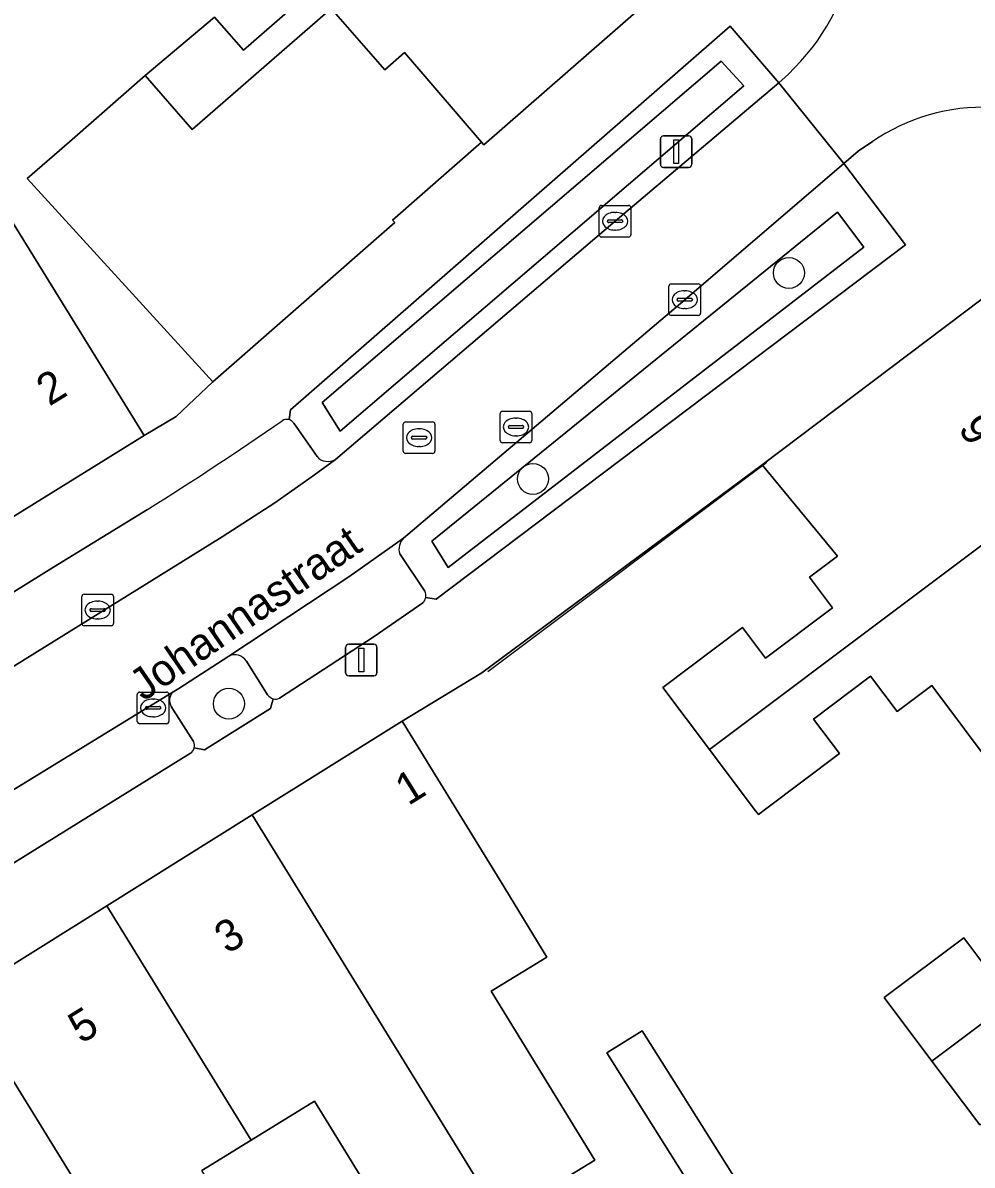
# Model space of a CAD drawing. Extents: x 159716 to 160783, y 383290 to 384031.
# Drawn here: x 160498.53 to 160528.52, y 383488.74 to 383524.87 of the extents above; entities that cross this region are included whole.
import ezdxf

# ---------------------------------------------------------------- set-up
doc = ezdxf.new("R2010")
doc.units = 0
for name, color, linetype in [('IMGEO_Boom', 7, 'Continuous'), ('IMGEO_Erf', 7, 'Continuous'), ('IMGEO_Groenvoorziening', 7, 'Continuous'), ('IMGEO_Kolk', 7, 'Continuous'), ('IMGEO_Lichtmast', 7, 'Continuous'), ('IMGEO_Muur', 7, 'Continuous'), ('IMGEO_Openbare_ruimte_label', 7, 'Continuous'), ('IMGEO_Pand', 7, 'Continuous'), ('IMGEO_Pand_nummerreeks', 7, 'Continuous'), ('IMGEO_Parkeervlak_open', 7, 'Continuous'), ('IMGEO_Rijbaan_lokaal_open', 7, 'Continuous'), ('IMGEO_Rioolput', 7, 'Continuous'), ('IMGEO_Voetpad_open', 7, 'Continuous')]:
    doc.layers.add(name, color=color, linetype=linetype)

msp = doc.modelspace()

# ---------------------------------------------------------------- linework, layer by layer
at = {"layer": 'IMGEO_Boom'}
for centre in [(160522.734, 383516.956), (160514.646, 383510.442), (160505.036, 383503.334)]:
    msp.add_circle(centre, 0.489, dxfattribs=at)
at = {"layer": 'IMGEO_Erf'}
for points in [[(160474.442, 383512.059), (160477.722, 383506.738), (160479.584, 383507.886), (160481.047, 383508.788), (160477.74, 383514.152), (160480.93, 383516.118), (160483.558, 383517.738), (160486.817, 383512.452), (160488.841, 383513.7), (160490.206, 383514.541), (160486.892, 383519.915), (160490.181, 383521.943), (160492.677, 383523.481), (160496.006, 383518.081), (160497.813, 383519.195), (160502.361, 383511.817), (160503.371, 383512.413), (160504.529, 383513.509), (160498.663, 383519.938), (160500, 383521.105), (160502.393, 383523.195), (160504.587, 383525.045), (160505.499, 383524.004), (160507.373, 383525.646)], [(160529.316, 383501.144), (160527.247, 383503.907), (160526.151, 383503.084), (160525.312, 383504.201), (160523.511, 383502.849), (160524.333, 383501.754), (160521.998, 383500), (160521.768, 383499.827), (160521.638, 383500), (160520.224, 383501.882), (160518.745, 383503.851), (160521.263, 383505.742), (160521.989, 383504.774), (160524.107, 383506.365), (160523.38, 383507.332), (160524.267, 383507.998), (160521.892, 383510.886), (160513.025, 383504.314), (160510.513, 383502.782), (160513.612, 383497.741), (160515.083, 383495.32), (160513.325, 383494.245), (160516.605, 383488.904), (160513.625, 383487.074)], [(160528.769, 383490.015), (160527.255, 383492.03), (160525.746, 383494.039), (160528.264, 383495.93), (160528.99, 383494.962)], [(160507.622, 383460.767), (160506.312, 383462.756), (160508.883, 383464.448), (160516.455, 383469.433), (160517.763, 383467.447), (160519.148, 383468.36), (160517.918, 383470.229), (160522.244, 383473.076), (160527.076, 383476.257), (160526.865, 383476.578), (160516.985, 383492.294), (160518.098, 383492.994), (160519.359, 383490.987), (160519.624, 383490.566), (160527.919, 383477.37), (160534.319, 383482.179)], [(160510.995, 383485.459), (160507.74, 383490.76), (160505.742, 383489.533), (160504.18, 383488.574)]]:
    msp.add_lwpolyline(points, dxfattribs=at)
at = {"layer": 'IMGEO_Groenvoorziening'}
for points in [[(160520.88, 383524.764), (160506.983, 383512.622), (160506.94, 383512.317)], [(160508.401, 383511.054), (160517.242, 383518.592), (160522.412, 383522.964), (160520.88, 383524.764)], [(160524.466, 383520.413), (160519.442, 383516.111), (160510.556, 383508.571)], [(160511.257, 383506.693), (160511.586, 383506.636), (160526.42, 383517.847), (160524.466, 383520.413)], [(160507.089, 383512.202), (160507.822, 383511.147)], [(160510.438, 383508.07), (160511.228, 383506.891)], [(160505.032, 383504.834), (160503.456, 383503.817), (160503.249, 383503.69)], [(160506.259, 383503.615), (160505.589, 383504.677)], [(160503.215, 383503.246), (160503.914, 383502.135)], [(160503.941, 383501.935), (160504.27, 383501.875), (160506.355, 383503.179), (160506.437, 383503.49)]]:
    msp.add_lwpolyline(points, dxfattribs=at)
for points in [[(160507.989, 383512.857), (160508.556, 383511.951), (160521.309, 383522.877), (160520.597, 383523.652)], [(160507.989, 383512.857), (160520.597, 383523.652), (160521.309, 383522.877), (160508.556, 383511.951)], [(160524.273, 383518.879), (160525.1, 383517.776), (160511.968, 383507.643), (160511.451, 383508.47)], [(160524.273, 383518.879), (160511.451, 383508.47), (160511.968, 383507.643), (160525.1, 383517.776)]]:
    msp.add_lwpolyline(points, close=True, dxfattribs=at)
for centre, radius, start, end in [((160506.869, 383512.071), 0.256, 30.8062, 73.871), ((160508.169, 383511.461), 0.468, 222.0892, 299.6608), ((160510.9, 383508.226), 0.488, 134.8926, 198.6008), ((160510.933, 383506.747), 0.328, 350.5796, 26.0855), ((160505.229, 383504.465), 0.418, 30.4255, 118.0917), ((160503.541, 383503.444), 0.382, 139.9262, 211.3159), ((160506.514, 383503.788), 0.308, 214.2592, 255.5842), ((160503.682, 383502.002), 0.268, 345.566, 29.8109)]:
    msp.add_arc(centre, radius, start, end, dxfattribs=at)
at = {"layer": 'IMGEO_Kolk'}
for p, q in [((160516.816, 383519.092), (160517.668, 383519.092)), ((160516.741, 383518.166), (160516.741, 383519.018)), ((160517.229, 383518.872), (160517.254, 383518.872)), ((160517.742, 383519.018), (160517.742, 383518.166)), ((160517, 383518.586), (160517, 383518.598)), ((160517.438, 383518.549), (160517.04, 383518.549)), ((160517.043, 383518.635), (160517.441, 383518.635)), ((160517.252, 383518.312), (160517.227, 383518.312)), ((160517.484, 383518.598), (160517.484, 383518.586)), ((160517.668, 383518.092), (160516.816, 383518.092)), ((160518.941, 383515.685), (160518.941, 383516.537)), ((160519.016, 383516.611), (160519.868, 383516.611)), ((160519.942, 383516.537), (160519.942, 383515.685)), ((160519.243, 383516.154), (160519.641, 383516.154)), ((160519.429, 383516.391), (160519.454, 383516.391)), ((160519.2, 383516.105), (160519.2, 383516.117)), ((160519.638, 383516.068), (160519.24, 383516.068)), ((160519.452, 383515.831), (160519.427, 383515.831)), ((160519.684, 383516.117), (160519.684, 383516.105)), ((160519.868, 383515.611), (160519.016, 383515.611)), ((160500.464, 383506.796), (160501.316, 383506.796)), ((160500.389, 383505.87), (160500.389, 383506.722)), ((160500.877, 383506.576), (160500.902, 383506.576)), ((160501.39, 383506.722), (160501.39, 383505.87)), ((160500.648, 383506.29), (160500.648, 383506.302)), ((160501.086, 383506.253), (160500.688, 383506.253)), ((160500.691, 383506.339), (160501.089, 383506.339)), ((160501.132, 383506.302), (160501.132, 383506.29)), ((160501.316, 383505.796), (160500.464, 383505.796)), ((160500.9, 383506.016), (160500.875, 383506.016)), ((160502.142, 383502.775), (160502.142, 383503.627)), ((160502.217, 383503.701), (160503.069, 383503.701)), ((160503.143, 383503.627), (160503.143, 383502.775)), ((160502.401, 383503.195), (160502.401, 383503.207)), ((160502.839, 383503.158), (160502.441, 383503.158)), ((160502.444, 383503.244), (160502.842, 383503.244)), ((160502.63, 383503.481), (160502.655, 383503.481)), ((160502.885, 383503.207), (160502.885, 383503.195)), ((160502.653, 383502.921), (160502.628, 383502.921)), ((160503.069, 383502.701), (160502.217, 383502.701))]:
    msp.add_line(p, q, dxfattribs=at)
for points in [[(160516.816, 383519.092), (160517.668, 383519.092)], [(160516.741, 383518.166), (160516.741, 383519.018)], [(160517.742, 383519.018), (160517.742, 383518.166)], [(160517.668, 383518.092), (160516.816, 383518.092)], [(160518.941, 383515.685), (160518.941, 383516.537)], [(160519.016, 383516.611), (160519.868, 383516.611)], [(160519.942, 383516.537), (160519.942, 383515.685)], [(160519.868, 383515.611), (160519.016, 383515.611)], [(160500.464, 383506.796), (160501.316, 383506.796)], [(160500.389, 383505.87), (160500.389, 383506.722)], [(160501.39, 383506.722), (160501.39, 383505.87)], [(160501.316, 383505.796), (160500.464, 383505.796)], [(160502.142, 383502.775), (160502.142, 383503.627)], [(160502.217, 383503.701), (160503.069, 383503.701)], [(160503.143, 383503.627), (160503.143, 383502.775)], [(160503.069, 383502.701), (160502.217, 383502.701)]]:
    msp.add_lwpolyline(points, dxfattribs=at)
for centre, radius, start, end in [((160516.818, 383519.016), 0.0765, 91.552, 178.448), ((160516.818, 383519.016), 0.0765, 91.552, 178.448), ((160517.666, 383519.016), 0.0765, 1.552, 88.448), ((160517.666, 383519.016), 0.0765, 1.552, 88.448), ((160517.04, 383518.595), 0.0403, 85.8775, 175.7526), ((160517.037, 383518.585), 0.0366, 178.938, 274.7102), ((160517.441, 383518.592), 0.043, 264.8664, 352.4533), ((160517.445, 383518.597), 0.0386, 1.7309, 96.639), ((160516.818, 383518.168), 0.0765, 181.552, 268.448), ((160516.818, 383518.168), 0.0765, 181.552, 268.448), ((160517.666, 383518.168), 0.0765, 271.552, 358.448), ((160517.666, 383518.168), 0.0765, 271.552, 358.448), ((160519.018, 383516.535), 0.0765, 91.552, 178.448), ((160519.018, 383516.535), 0.0765, 91.552, 178.448), ((160519.866, 383516.535), 0.0765, 1.552, 88.448), ((160519.866, 383516.535), 0.0765, 1.552, 88.448), ((160519.24, 383516.114), 0.0403, 85.8775, 175.7526), ((160519.645, 383516.116), 0.0386, 1.7309, 96.639), ((160519.237, 383516.104), 0.0366, 178.938, 274.7102), ((160519.641, 383516.111), 0.043, 264.8664, 352.4533), ((160519.018, 383515.687), 0.0765, 181.552, 268.448), ((160519.018, 383515.687), 0.0765, 181.552, 268.448), ((160519.866, 383515.687), 0.0765, 271.552, 358.448), ((160519.866, 383515.687), 0.0765, 271.552, 358.448), ((160500.466, 383506.72), 0.0765, 91.552, 178.448), ((160500.466, 383506.72), 0.0765, 91.552, 178.448), ((160501.314, 383506.72), 0.0765, 1.552, 88.448), ((160501.314, 383506.72), 0.0765, 1.552, 88.448), ((160500.688, 383506.299), 0.0403, 85.8775, 175.7526), ((160500.685, 383506.289), 0.0366, 178.938, 274.7102), ((160501.089, 383506.296), 0.043, 264.8664, 352.4533), ((160501.093, 383506.301), 0.0386, 1.7309, 96.639), ((160500.466, 383505.872), 0.0765, 181.552, 268.448), ((160500.466, 383505.872), 0.0765, 181.552, 268.448), ((160501.314, 383505.872), 0.0765, 271.552, 358.448), ((160501.314, 383505.872), 0.0765, 271.552, 358.448), ((160502.219, 383503.625), 0.0765, 91.552, 178.448), ((160502.219, 383503.625), 0.0765, 91.552, 178.448), ((160503.067, 383503.625), 0.0765, 1.552, 88.448), ((160503.067, 383503.625), 0.0765, 1.552, 88.448), ((160502.441, 383503.204), 0.0403, 85.8775, 175.7526), ((160502.438, 383503.194), 0.0366, 178.938, 274.7102), ((160502.842, 383503.201), 0.043, 264.8664, 352.4533), ((160502.846, 383503.206), 0.0386, 1.7309, 96.639), ((160502.219, 383502.777), 0.0765, 181.552, 268.448), ((160502.219, 383502.777), 0.0765, 181.552, 268.448), ((160503.067, 383502.777), 0.0765, 271.552, 358.448), ((160503.067, 383502.777), 0.0765, 271.552, 358.448)]:
    msp.add_arc(centre, radius, start, end, dxfattribs=at)
for centre, major_axis, ratio, start_param, end_param in [((160517.228, 383518.592), (-0.387, 0.002), 0.722429, 4.712389, 7.853982), ((160517.253, 383518.592), (-0.39, 0.002), 0.717154, 1.570796, 4.712389), ((160519.428, 383516.111), (-0.387, 0.002), 0.722429, 4.712389, 7.853982), ((160519.453, 383516.111), (-0.39, 0.002), 0.717154, 1.570796, 4.712389), ((160500.876, 383506.296), (-0.387, 0.002), 0.722429, 4.712389, 7.853982), ((160500.901, 383506.296), (-0.39, 0.002), 0.717154, 1.570796, 4.712389), ((160502.629, 383503.201), (-0.387, 0.002), 0.722429, 4.712389, 7.853982), ((160502.654, 383503.201), (-0.39, 0.002), 0.717154, 1.570796, 4.712389)]:
    msp.add_ellipse(centre, major_axis=major_axis, ratio=ratio, start_param=start_param, end_param=end_param, dxfattribs=at)
at = {"layer": 'IMGEO_Lichtmast'}
for p, q in [((160518.773, 383521.292), (160519.563, 383521.292)), ((160519.563, 383521.292), (160518.773, 383521.292)), ((160518.673, 383520.392), (160518.673, 383521.192)), ((160518.673, 383521.192), (160518.673, 383520.392)), ((160519.663, 383521.192), (160519.663, 383520.392)), ((160519.663, 383520.392), (160519.663, 383521.192)), ((160519.563, 383520.292), (160518.773, 383520.292)), ((160518.773, 383520.292), (160519.563, 383520.292)), ((160508.726, 383504.315), (160508.726, 383505.115)), ((160508.726, 383505.115), (160508.726, 383504.315)), ((160508.826, 383505.215), (160509.616, 383505.215)), ((160509.616, 383505.215), (160508.826, 383505.215)), ((160509.716, 383505.115), (160509.716, 383504.315)), ((160509.716, 383504.315), (160509.716, 383505.115)), ((160509.616, 383504.215), (160508.826, 383504.215)), ((160508.826, 383504.215), (160509.616, 383504.215))]:
    msp.add_line(p, q, dxfattribs=at)
for points in [[(160519.093, 383521.167), (160519.243, 383521.167), (160519.243, 383520.417), (160519.093, 383520.417), (160519.093, 383521.167)], [(160509.146, 383505.09), (160509.296, 383505.09), (160509.296, 383504.34), (160509.146, 383504.34), (160509.146, 383505.09)]]:
    msp.add_lwpolyline(points, dxfattribs=at)
for centre, start, end in [((160518.773, 383521.192), 90, 180), ((160518.773, 383521.192), 90, 180), ((160519.563, 383521.192), 0, 90), ((160519.563, 383521.192), 360, 90), ((160518.773, 383520.392), 180, 270), ((160518.773, 383520.392), 180, 270), ((160519.563, 383520.392), 270, 0), ((160519.563, 383520.392), 270, 0), ((160508.826, 383505.115), 90, 180), ((160508.826, 383505.115), 90, 180), ((160509.616, 383505.115), 0, 90), ((160509.616, 383505.115), 360, 90), ((160508.826, 383504.315), 180, 270), ((160508.826, 383504.315), 180, 270), ((160509.616, 383504.315), 270, 0), ((160509.616, 383504.315), 270, 0)]:
    msp.add_arc(centre, 0.1, start, end, dxfattribs=at)
at = {"layer": 'IMGEO_Muur'}
msp.add_lwpolyline([(160522.039, 383510.964), (160513.219, 383504.34)], dxfattribs=at)
at = {"layer": 'IMGEO_Pand'}
for points in [[(160515.423, 383531.566), (160511.739, 383535.776), (160505.167, 383530.053), (160507.361, 383527.534), (160506.433, 383526.723), (160507.373, 383525.646), (160505.499, 383524.004), (160504.587, 383525.045), (160502.393, 383523.195), (160503.879, 383521.493), (160507.921, 383525.017), (160508.268, 383525.319)], [(160519.644, 383526.744), (160515.423, 383531.566), (160508.268, 383525.319), (160509.96, 383523.378), (160510.589, 383523.926), (160513.021, 383521.09), (160513.093, 383521.008)], [(160513.021, 383521.09), (160510.589, 383523.926), (160509.96, 383523.378), (160508.268, 383525.319), (160507.921, 383525.017), (160503.879, 383521.493), (160502.393, 383523.195), (160500, 383521.105), (160498.663, 383519.938), (160504.529, 383513.509), (160510.281, 383518.547), (160510.208, 383518.63)], [(160497.813, 383519.195), (160496.006, 383518.081), (160492.677, 383523.481), (160490.181, 383521.943), (160498.066, 383509.151), (160502.361, 383511.817)], [(160532.589, 383511.169), (160528.836, 383516.141), (160521.892, 383510.886), (160524.267, 383507.998), (160523.38, 383507.332), (160524.107, 383506.365), (160521.989, 383504.774), (160521.263, 383505.742), (160518.745, 383503.851), (160520.224, 383501.882)], [(160536.235, 383506.34), (160532.589, 383511.169), (160520.224, 383501.882), (160521.638, 383500), (160521.768, 383499.827), (160521.998, 383500), (160524.333, 383501.754), (160523.511, 383502.849), (160525.312, 383504.201), (160526.151, 383503.084), (160527.247, 383503.907), (160529.316, 383501.144)], [(160537.868, 383500), (160539.88, 383501.511), (160536.235, 383506.34), (160529.316, 383501.144), (160530.173, 383500), (160531.371, 383498.401), (160530.314, 383497.605), (160531.105, 383496.551), (160528.99, 383494.962), (160528.264, 383495.93), (160525.746, 383494.039), (160527.255, 383492.03), (160531.888, 383495.509)], [(160515.083, 383495.32), (160513.612, 383497.741), (160510.513, 383502.782), (160505.777, 383499.821), (160513.625, 383487.074), (160516.605, 383488.904), (160513.325, 383494.245)], [(160543.596, 383496.588), (160539.88, 383501.511), (160537.868, 383500), (160531.888, 383495.509), (160527.255, 383492.03), (160528.769, 383490.015), (160531.334, 383491.942), (160530.512, 383493.037), (160532.579, 383494.589), (160533.435, 383493.45), (160534.484, 383494.237), (160536.65, 383491.353)], [(160505.777, 383499.821), (160501.178, 383496.945), (160505.742, 383489.533), (160507.74, 383490.76), (160510.995, 383485.459), (160513.625, 383487.074)], [(160505.742, 383489.533), (160501.178, 383496.945), (160496.58, 383494.069), (160500, 383488.516), (160504.391, 383481.385), (160504.71, 383481.58), (160507.444, 383483.258), (160504.18, 383488.574)], [(160500, 383488.516), (160496.58, 383494.069), (160491.982, 383491.194), (160496.493, 383483.868), (160498.462, 383485.076), (160500, 383482.559), (160501.719, 383479.746), (160502.854, 383480.442), (160504.391, 383481.385)]]:
    msp.add_lwpolyline(points, close=True, dxfattribs=at)
at = {"layer": 'IMGEO_Parkeervlak_open'}
for points in [[(160507.822, 383511.147), (160507.089, 383512.202)], [(160492.049, 383500.676), (160494.972, 383502.492), (160504.828, 383508.614), (160506.49, 383509.69), (160507.743, 383510.567), (160508.401, 383511.054)], [(160502.461, 383509.473), (160499.497, 383507.648), (160476.969, 383493.644)], [(160510.556, 383508.571), (160508.822, 383507.344), (160505.032, 383504.834)], [(160511.228, 383506.891), (160510.438, 383508.07)], [(160506.636, 383503.504), (160509.627, 383505.461), (160511.168, 383506.52)], [(160505.589, 383504.677), (160506.259, 383503.615)], [(160503.249, 383503.69), (160496.699, 383499.682), (160493.79, 383497.878), (160487.816, 383494.171)], [(160503.914, 383502.135), (160503.215, 383503.246)], [(160489.45, 383492.842), (160503.826, 383501.773)]]:
    msp.add_lwpolyline(points, dxfattribs=at)
for centre, radius, start, end in [((160440.404, 383608.321), 116.714, 302.12079, 304.62339), ((160506.869, 383512.074), 0.253, 73.794, 126.6339), ((160506.869, 383512.071), 0.256, 30.8062, 73.871), ((160508.169, 383511.461), 0.468, 222.0892, 299.6608), ((160510.9, 383508.226), 0.488, 134.8926, 198.6008), ((160510.933, 383506.747), 0.328, 350.5796, 26.0855), ((160510.938, 383506.748), 0.323, 315.2692, 350.2836), ((160505.229, 383504.465), 0.418, 30.4255, 118.0917), ((160503.541, 383503.444), 0.382, 139.9262, 211.3159), ((160506.514, 383503.788), 0.308, 214.2592, 255.5842), ((160506.515, 383503.798), 0.318, 255.7242, 292.3243), ((160503.682, 383502.002), 0.268, 345.566, 29.8109), ((160503.68, 383501.999), 0.269, 302.9658, 346.2941)]:
    msp.add_arc(centre, radius, start, end, dxfattribs=at)
at = {"layer": 'IMGEO_Rijbaan_lokaal_open'}
msp.add_lwpolyline([(160523.106, 383523.653), (160522.72, 383523.238), (160522.412, 383522.964), (160524.466, 383520.413), (160524.926, 383520.807), (160525.375, 383521.115)], dxfattribs=at)
msp.add_lwpolyline([(160522.412, 383522.964), (160517.242, 383518.592), (160508.401, 383511.054), (160507.743, 383510.567), (160506.49, 383509.69), (160504.828, 383508.614), (160494.972, 383502.492), (160496.699, 383499.682), (160503.249, 383503.69), (160503.456, 383503.817), (160505.032, 383504.834), (160508.822, 383507.344), (160510.556, 383508.571), (160519.442, 383516.111), (160524.466, 383520.413)], close=True, dxfattribs=at)
for centre, radius, start, end in [((160518.349, 383528.058), 6.484, 317.2011, 356.329), ((160528.885, 383515.966), 6.231, 87.8013, 124.2831)]:
    msp.add_arc(centre, radius, start, end, dxfattribs=at)
at = {"layer": 'IMGEO_Rioolput'}
for p, q in [((160513.684, 383512.585), (160514.536, 383512.585)), ((160510.548, 383511.321), (160510.548, 383512.173)), ((160510.623, 383512.247), (160511.475, 383512.247)), ((160511.549, 383512.173), (160511.549, 383511.321)), ((160513.609, 383511.659), (160513.609, 383512.511)), ((160514.097, 383512.365), (160514.122, 383512.365)), ((160514.61, 383512.511), (160514.61, 383511.659)), ((160511.036, 383512.027), (160511.061, 383512.027)), ((160513.868, 383512.079), (160513.868, 383512.091)), ((160514.306, 383512.042), (160513.908, 383512.042)), ((160513.911, 383512.128), (160514.309, 383512.128)), ((160514.352, 383512.091), (160514.352, 383512.079)), ((160510.807, 383511.741), (160510.807, 383511.753)), ((160511.245, 383511.704), (160510.847, 383511.704)), ((160510.85, 383511.79), (160511.248, 383511.79)), ((160511.059, 383511.467), (160511.034, 383511.467)), ((160511.291, 383511.753), (160511.291, 383511.741)), ((160514.536, 383511.585), (160513.684, 383511.585)), ((160514.12, 383511.805), (160514.095, 383511.805)), ((160511.475, 383511.247), (160510.623, 383511.247))]:
    msp.add_line(p, q, dxfattribs=at)
for points in [[(160513.684, 383512.585), (160514.536, 383512.585)], [(160510.548, 383511.321), (160510.548, 383512.173)], [(160510.623, 383512.247), (160511.475, 383512.247)], [(160511.549, 383512.173), (160511.549, 383511.321)], [(160513.609, 383511.659), (160513.609, 383512.511)], [(160514.61, 383512.511), (160514.61, 383511.659)], [(160514.536, 383511.585), (160513.684, 383511.585)], [(160511.475, 383511.247), (160510.623, 383511.247)]]:
    msp.add_lwpolyline(points, dxfattribs=at)
for centre, radius, start, end in [((160513.686, 383512.509), 0.0765, 91.552, 178.448), ((160513.686, 383512.509), 0.0765, 91.552, 178.448), ((160514.534, 383512.509), 0.0765, 1.552, 88.448), ((160514.534, 383512.509), 0.0765, 1.552, 88.448), ((160510.625, 383512.171), 0.0765, 91.552, 178.448), ((160510.625, 383512.171), 0.0765, 91.552, 178.448), ((160511.473, 383512.171), 0.0765, 1.552, 88.448), ((160511.473, 383512.171), 0.0765, 1.552, 88.448), ((160513.908, 383512.088), 0.0403, 85.8775, 175.7526), ((160513.905, 383512.078), 0.0366, 178.938, 274.7102), ((160514.309, 383512.085), 0.043, 264.8664, 352.4533), ((160514.313, 383512.09), 0.0386, 1.7309, 96.639), ((160510.847, 383511.75), 0.0403, 85.8775, 175.7526), ((160510.844, 383511.74), 0.0366, 178.938, 274.7102), ((160511.248, 383511.747), 0.043, 264.8664, 352.4533), ((160511.252, 383511.752), 0.0386, 1.7309, 96.639), ((160513.686, 383511.661), 0.0765, 181.552, 268.448), ((160513.686, 383511.661), 0.0765, 181.552, 268.448), ((160514.534, 383511.661), 0.0765, 271.552, 358.448), ((160514.534, 383511.661), 0.0765, 271.552, 358.448), ((160510.625, 383511.323), 0.0765, 181.552, 268.448), ((160510.625, 383511.323), 0.0765, 181.552, 268.448), ((160511.473, 383511.323), 0.0765, 271.552, 358.448), ((160511.473, 383511.323), 0.0765, 271.552, 358.448)]:
    msp.add_arc(centre, radius, start, end, dxfattribs=at)
for centre, major_axis, ratio, start_param, end_param in [((160514.096, 383512.085), (-0.387, 0.002), 0.722429, 4.712389, 7.853982), ((160514.121, 383512.085), (-0.39, 0.002), 0.717154, 1.570796, 4.712389), ((160511.035, 383511.747), (-0.387, 0.002), 0.722429, 4.712389, 7.853982), ((160511.06, 383511.747), (-0.39, 0.002), 0.717154, 1.570796, 4.712389)]:
    msp.add_ellipse(centre, major_axis=major_axis, ratio=ratio, start_param=start_param, end_param=end_param, dxfattribs=at)
at = {"layer": 'IMGEO_Voetpad_open'}
for points in [[(160519.644, 383526.744), (160513.093, 383521.008), (160513.021, 383521.09), (160510.208, 383518.63), (160510.281, 383518.547), (160504.529, 383513.509), (160503.371, 383512.413), (160502.361, 383511.817), (160498.066, 383509.151), (160493.423, 383506.269), (160488.779, 383503.386), (160484.135, 383500.503), (160479.491, 383497.62), (160474.684, 383494.636)], [(160506.94, 383512.317), (160506.983, 383512.622), (160520.88, 383524.764), (160522.412, 383522.964), (160522.72, 383523.238), (160523.106, 383523.653)], [(160525.375, 383521.115), (160524.926, 383520.807), (160524.466, 383520.413), (160526.42, 383517.847), (160511.586, 383506.636), (160511.257, 383506.693)], [(160432.435, 383460.679), (160437.405, 383462.822), (160442.373, 383464.964), (160447.343, 383467.106), (160452.408, 383469.29), (160453.253, 383469.701), (160457.967, 383472.21), (160462.733, 383474.747), (160467.502, 383477.285), (160472.268, 383479.822), (160477.037, 383482.36), (160478.241, 383483.001), (160480.377, 383484.144), (160482.026, 383485.026), (160482.856, 383485.488), (160487.383, 383488.318), (160491.982, 383491.194), (160496.58, 383494.069), (160501.178, 383496.945), (160505.777, 383499.821), (160510.513, 383502.782), (160513.025, 383504.314), (160521.892, 383510.886), (160528.836, 383516.141)], [(160476.969, 383493.644), (160499.497, 383507.648), (160502.461, 383509.473)], [(160511.168, 383506.52), (160509.627, 383505.461), (160506.636, 383503.504)], [(160506.437, 383503.49), (160506.355, 383503.179), (160504.27, 383501.875), (160503.941, 383501.935)], [(160503.826, 383501.773), (160489.45, 383492.842)], [(160534.319, 383482.179), (160527.919, 383477.37), (160519.624, 383490.566), (160519.359, 383490.987), (160518.098, 383492.994), (160516.985, 383492.294), (160526.865, 383476.578), (160527.076, 383476.257), (160527.195, 383476.335), (160528.474, 383474.392), (160523.523, 383471.133), (160519.197, 383468.286), (160519.148, 383468.36), (160517.763, 383467.447), (160517.861, 383467.298), (160510.288, 383462.313), (160507.718, 383460.621)]]:
    msp.add_lwpolyline(points, dxfattribs=at)
for centre, radius, start, end in [((160518.349, 383528.058), 6.484, 317.2011, 356.329), ((160528.885, 383515.966), 6.231, 87.8013, 124.2831), ((160440.404, 383608.321), 116.714, 302.12079, 304.62339), ((160506.869, 383512.074), 0.253, 73.794, 126.6339), ((160510.938, 383506.748), 0.323, 315.2692, 350.2836), ((160506.515, 383503.798), 0.318, 255.7242, 292.3243), ((160503.68, 383501.999), 0.269, 302.9658, 346.2941)]:
    msp.add_arc(centre, radius, start, end, dxfattribs=at)

# ---------------------------------------------------------------- texts
at = {"layer": 'IMGEO_Openbare_ruimte_label'}
msp.add_text('Johannastraat', height=1, rotation=34.6118, dxfattribs=at).set_placement((160502.34, 383503.391))
at = {"layer": 'IMGEO_Pand_nummerreeks'}
for s, rotation, p in [('2', 31.6559, (160499.362, 383512.725)), ('9', 306.9097, (160528.052, 383512.014)), ('1', 31.9137, (160510.704, 383500.092)), ('3', 31.5872, (160504.987, 383495.4)), ('5', 31.5814, (160500.367, 383492.559))]:
    msp.add_text(s, height=1, rotation=rotation, dxfattribs=at).set_placement(p)

doc.saveas('drawing.dxf')
